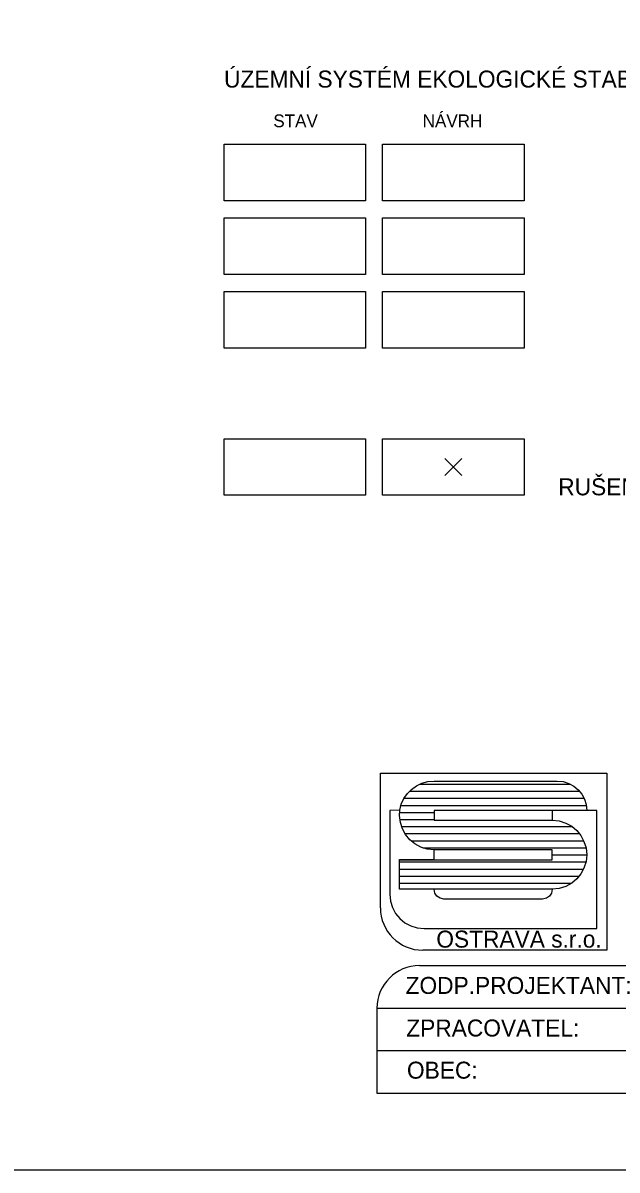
# Model space of a CAD drawing. Extents: x -557942 to -541772, y -1047288 to -1036007.
# Drawn here: x -554032 to -553613, y -1039374 to -1038564 of the extents above; entities that cross this region are included whole.
import ezdxf

# ---------------------------------------------------------------- set-up
doc = ezdxf.new("R2010")
doc.units = 0
doc.layers.add('ft_08_PLN_plyn_sit_l_STL_STAV', color=7, linetype='Continuous')
doc.layers.add('Vrstva 1', color=7, linetype='Continuous')

msp = doc.modelspace()

# ---------------------------------------------------------------- linework, layer by layer
at = {"layer": 'ft_08_PLN_plyn_sit_l_STL_STAV'}
for p, q in [((-553734.35, -1038871.23), (-553722.35, -1038883.23)), ((-553722.35, -1038871.23), (-553734.35, -1038883.23))]:
    msp.add_line(p, q, dxfattribs=at)
at = {"layer": 'Vrstva 1'}
for p, q in [((-553751.87, -1039101.23), (-553645.96, -1039101.23)), ((-553751.87, -1039101.23), (-553645.96, -1039101.23)), ((-553759.2, -1039106.23), (-553639.48, -1039106.23)), ((-553759.2, -1039106.23), (-553639.48, -1039106.23)), ((-553765.4, -1039116.23), (-553634.6, -1039116.23)), ((-553765.4, -1039116.23), (-553634.6, -1039116.23)), ((-553763.22, -1039111.23), (-553636.17, -1039111.23)), ((-553763.22, -1039111.23), (-553636.17, -1039111.23)), ((-553766.28, -1039121.23), (-553742.04, -1039121.23)), ((-553766.28, -1039121.23), (-553742.04, -1039121.23)), ((-553766.06, -1039126.23), (-553742.04, -1039126.23)), ((-553766.06, -1039126.23), (-553742.04, -1039126.23)), ((-553764.93, -1039131.23), (-553644.57, -1039131.23)), ((-553764.93, -1039131.23), (-553644.57, -1039131.23)), ((-553762.53, -1039136.23), (-553639.42, -1039136.23)), ((-553762.53, -1039136.23), (-553639.42, -1039136.23)), ((-553758.33, -1039141.23), (-553636.41, -1039141.23)), ((-553758.33, -1039141.23), (-553636.41, -1039141.23)), ((-553750, -1039146.23), (-553634.76, -1039146.23)), ((-553750, -1039146.23), (-553634.76, -1039146.23)), ((-553766.34, -1039156.23), (-553634.83, -1039156.23)), ((-553766.34, -1039156.23), (-553634.83, -1039156.23)), ((-553658.57, -1039151.23), (-553634.28, -1039151.23)), ((-553658.57, -1039151.23), (-553634.28, -1039151.23)), ((-553766.34, -1039161.23), (-553636.55, -1039161.23)), ((-553766.34, -1039161.23), (-553636.55, -1039161.23)), ((-553766.34, -1039166.23), (-553639.67, -1039166.23)), ((-553766.34, -1039166.23), (-553639.67, -1039166.23)), ((-553766.34, -1039171.23), (-553644.89, -1039171.23)), ((-553766.34, -1039171.23), (-553644.89, -1039171.23)), ((-553752.35, -1039229.45), (-552902.35, -1039229.45)), ((-553752.35, -1039229.45), (-552902.35, -1039229.45)), ((-553782.35, -1039259.45), (-552902.35, -1039259.45)), ((-553782.35, -1039259.45), (-553782.35, -1039319.45)), ((-553782.35, -1039259.45), (-552902.35, -1039259.45)), ((-553782.35, -1039259.45), (-553782.35, -1039319.45)), ((-553782.35, -1039289.45), (-552902.35, -1039289.45)), ((-553782.35, -1039289.45), (-552902.35, -1039289.45)), ((-553782.35, -1039319.45), (-552902.35, -1039319.45)), ((-553782.35, -1039319.45), (-552902.35, -1039319.45))]:
    msp.add_line(p, q, dxfattribs=at)
for points in [[(-552782.35, -1036132.71), (-552782.35, -1039373.85), (-555282.35, -1039373.85), (-555282.35, -1036132.71)], [(-553890.35, -1038649.23), (-553790.35, -1038649.23), (-553790.35, -1038689.23), (-553890.35, -1038689.23)], [(-553778.35, -1038649.23), (-553678.35, -1038649.23), (-553678.35, -1038689.23), (-553778.35, -1038689.23)], [(-553890.35, -1038701.23), (-553790.35, -1038701.23), (-553790.35, -1038741.23), (-553890.35, -1038741.23)], [(-553778.35, -1038701.23), (-553678.35, -1038701.23), (-553678.35, -1038741.23), (-553778.35, -1038741.23)], [(-553890.35, -1038753.23), (-553790.35, -1038753.23), (-553790.35, -1038793.23), (-553890.35, -1038793.23)], [(-553778.35, -1038753.23), (-553678.35, -1038753.23), (-553678.35, -1038793.23), (-553778.35, -1038793.23)], [(-553890.35, -1038857.23), (-553790.35, -1038857.23), (-553790.35, -1038897.23), (-553890.35, -1038897.23)], [(-553778.35, -1038857.23), (-553678.35, -1038857.23), (-553678.35, -1038897.23), (-553778.35, -1038897.23)]]:
    msp.add_lwpolyline(points, close=True, dxfattribs=at)
for points in [[(-553779.96, -1039188.55), (-553779.96, -1039093.55), (-553619.96, -1039093.55), (-553619.96, -1039218.55), (-553749.96, -1039218.55)], [(-553779.96, -1039188.55), (-553779.96, -1039093.55), (-553619.96, -1039093.55), (-553619.96, -1039218.55), (-553749.96, -1039218.55)], [(-553658.57, -1039119.95), (-553742.04, -1039119.95), (-553742.04, -1039126.8), (-553658.57, -1039126.8), (-553653.62, -1039127.28), (-553649.04, -1039128.71), (-553644.85, -1039131), (-553641.32, -1039133.95), (-553638.37, -1039137.48), (-553636.18, -1039141.67), (-553634.75, -1039146.24), (-553634.27, -1039151.1), (-553634.75, -1039155.96), (-553636.18, -1039160.54), (-553638.37, -1039164.63), (-553641.32, -1039168.25), (-553644.85, -1039171.21), (-553649.04, -1039173.5), (-553653.62, -1039174.92), (-553658.57, -1039175.4), (-553742.04, -1039175.4), (-553766.34, -1039175.4), (-553766.34, -1039154.63), (-553742.04, -1039154.63), (-553658.57, -1039154.63), (-553658.57, -1039147.67), (-553742.04, -1039147.67), (-553746.9, -1039147.2), (-553751.48, -1039145.77), (-553755.57, -1039143.48), (-553759.19, -1039140.53), (-553762.15, -1039136.91), (-553764.44, -1039132.81), (-553765.86, -1039128.23), (-553766.34, -1039123.37), (-553766.24, -1039119.75), (-553765.2, -1039115.37), (-553763.39, -1039111.46), (-553760.91, -1039107.94), (-553757.96, -1039104.98), (-553754.43, -1039102.51), (-553750.62, -1039100.6), (-553746.43, -1039099.46), (-553742.04, -1039099.08), (-553655.14, -1039099.08), (-553650.85, -1039099.46), (-553646.95, -1039100.7), (-553643.42, -1039102.6), (-553640.37, -1039105.17), (-553637.8, -1039108.22), (-553635.89, -1039111.75), (-553634.65, -1039115.66), (-553634.27, -1039119.95), (-553658.57, -1039119.95)], [(-553658.57, -1039119.95), (-553742.04, -1039119.95), (-553742.04, -1039126.8), (-553658.57, -1039126.8), (-553653.62, -1039127.28), (-553649.04, -1039128.71), (-553644.85, -1039131), (-553641.32, -1039133.95), (-553638.37, -1039137.48), (-553636.18, -1039141.67), (-553634.75, -1039146.24), (-553634.27, -1039151.1), (-553634.75, -1039155.96), (-553636.18, -1039160.54), (-553638.37, -1039164.63), (-553641.32, -1039168.25), (-553644.85, -1039171.21), (-553649.04, -1039173.5), (-553653.62, -1039174.92), (-553658.57, -1039175.4), (-553742.04, -1039175.4), (-553766.34, -1039175.4), (-553766.34, -1039154.63), (-553742.04, -1039154.63), (-553658.57, -1039154.63), (-553658.57, -1039147.67), (-553742.04, -1039147.67), (-553746.9, -1039147.2), (-553751.48, -1039145.77), (-553755.57, -1039143.48), (-553759.19, -1039140.53), (-553762.15, -1039136.91), (-553764.44, -1039132.81), (-553765.86, -1039128.23), (-553766.34, -1039123.37), (-553766.24, -1039119.75), (-553765.2, -1039115.37), (-553763.39, -1039111.46), (-553760.91, -1039107.94), (-553757.96, -1039104.98), (-553754.43, -1039102.51), (-553750.62, -1039100.6), (-553746.43, -1039099.46), (-553742.04, -1039099.08), (-553655.14, -1039099.08), (-553650.85, -1039099.46), (-553646.95, -1039100.7), (-553643.42, -1039102.6), (-553640.37, -1039105.17), (-553637.8, -1039108.22), (-553635.89, -1039111.75), (-553634.65, -1039115.66), (-553634.27, -1039119.95), (-553658.57, -1039119.95)], [(-553627.22, -1039203.32), (-553627.22, -1039119.85), (-553634.27, -1039119.85), (-553658.57, -1039119.85), (-553658.57, -1039126.8), (-553653.62, -1039127.28), (-553649.04, -1039128.71), (-553644.85, -1039131), (-553641.32, -1039133.95), (-553638.37, -1039137.48), (-553636.18, -1039141.67), (-553634.75, -1039146.24), (-553634.27, -1039151.1), (-553634.75, -1039155.96), (-553636.18, -1039160.54), (-553638.37, -1039164.63), (-553641.32, -1039168.25), (-553644.85, -1039171.21), (-553649.04, -1039173.5), (-553653.62, -1039174.92), (-553658.57, -1039175.4), (-553659.14, -1039178.16), (-553660.57, -1039180.36), (-553662.76, -1039181.88), (-553665.43, -1039182.45), (-553735.08, -1039182.45), (-553737.85, -1039181.88), (-553740.04, -1039180.36), (-553741.47, -1039178.16), (-553742.04, -1039175.4), (-553766.34, -1039175.4), (-553766.34, -1039154.53), (-553742.04, -1039154.53), (-553742.04, -1039147.67), (-553746.9, -1039147.2), (-553751.48, -1039145.77), (-553755.57, -1039143.48), (-553759.19, -1039140.53), (-553762.15, -1039136.91), (-553764.44, -1039132.81), (-553765.86, -1039128.23), (-553766.34, -1039123.37), (-553766.24, -1039119.75), (-553773.39, -1039119.85), (-553773.39, -1039179.02), (-553772.92, -1039183.88), (-553771.49, -1039188.45), (-553769.2, -1039192.55), (-553766.24, -1039196.18), (-553762.62, -1039199.13), (-553758.53, -1039201.41), (-553753.95, -1039202.84), (-553749.09, -1039203.32), (-553748.9, -1039203.32), (-553627.22, -1039203.32)], [(-553627.22, -1039203.32), (-553627.22, -1039119.85), (-553634.27, -1039119.85), (-553658.57, -1039119.85), (-553658.57, -1039126.8), (-553653.62, -1039127.28), (-553649.04, -1039128.71), (-553644.85, -1039131), (-553641.32, -1039133.95), (-553638.37, -1039137.48), (-553636.18, -1039141.67), (-553634.75, -1039146.24), (-553634.27, -1039151.1), (-553634.75, -1039155.96), (-553636.18, -1039160.54), (-553638.37, -1039164.63), (-553641.32, -1039168.25), (-553644.85, -1039171.21), (-553649.04, -1039173.5), (-553653.62, -1039174.92), (-553658.57, -1039175.4), (-553659.14, -1039178.16), (-553660.57, -1039180.36), (-553662.76, -1039181.88), (-553665.43, -1039182.45), (-553735.08, -1039182.45), (-553737.85, -1039181.88), (-553740.04, -1039180.36), (-553741.47, -1039178.16), (-553742.04, -1039175.4), (-553766.34, -1039175.4), (-553766.34, -1039154.53), (-553742.04, -1039154.53), (-553742.04, -1039147.67), (-553746.9, -1039147.2), (-553751.48, -1039145.77), (-553755.57, -1039143.48), (-553759.19, -1039140.53), (-553762.15, -1039136.91), (-553764.44, -1039132.81), (-553765.86, -1039128.23), (-553766.34, -1039123.37), (-553766.24, -1039119.75), (-553773.39, -1039119.85), (-553773.39, -1039179.02), (-553772.92, -1039183.88), (-553771.49, -1039188.45), (-553769.2, -1039192.55), (-553766.24, -1039196.18), (-553762.62, -1039199.13), (-553758.53, -1039201.41), (-553753.95, -1039202.84), (-553749.09, -1039203.32), (-553748.9, -1039203.32), (-553627.22, -1039203.32)]]:
    msp.add_lwpolyline(points, dxfattribs=at)
for centre, start, end in [((-553749.97, -1039188.55), 180, 270), ((-553749.97, -1039188.55), 180, 270), ((-553752.35, -1039259.44), 90, 180), ((-553752.35, -1039259.44), 90, 180)]:
    msp.add_arc(centre, 30, start, end, dxfattribs=at)

# ---------------------------------------------------------------- texts
for s, height, p in [('ÚZEMNÍ SYSTÉM EKOLOGICKÉ STABILITY', 12, (-553890.35, -1038609.21)), ('STAV', 9, (-553855.56, -1038637.21)), ('NÁVRH', 9, (-553750.08, -1038637.21)), ('RUŠENÉ JEVY', 12, (-553654.35, -1038897.23)), ('OSTRAVA s.r.o.', 12, (-553740.46, -1039216.72)), ('OSTRAVA s.r.o.', 12, (-553740.46, -1039216.72)), ('ZODP.PROJEKTANT:', 12, (-553762.15, -1039249.44)), ('ZPRACOVATEL:', 12, (-553761.67, -1039279.51)), ('ZPRACOVATEL:', 12, (-553761.67, -1039279.51)), ('OBEC:', 12, (-553761.19, -1039309.28))]:
    msp.add_text(s, height=height, dxfattribs=at).set_placement(p)

doc.saveas('drawing.dxf')
